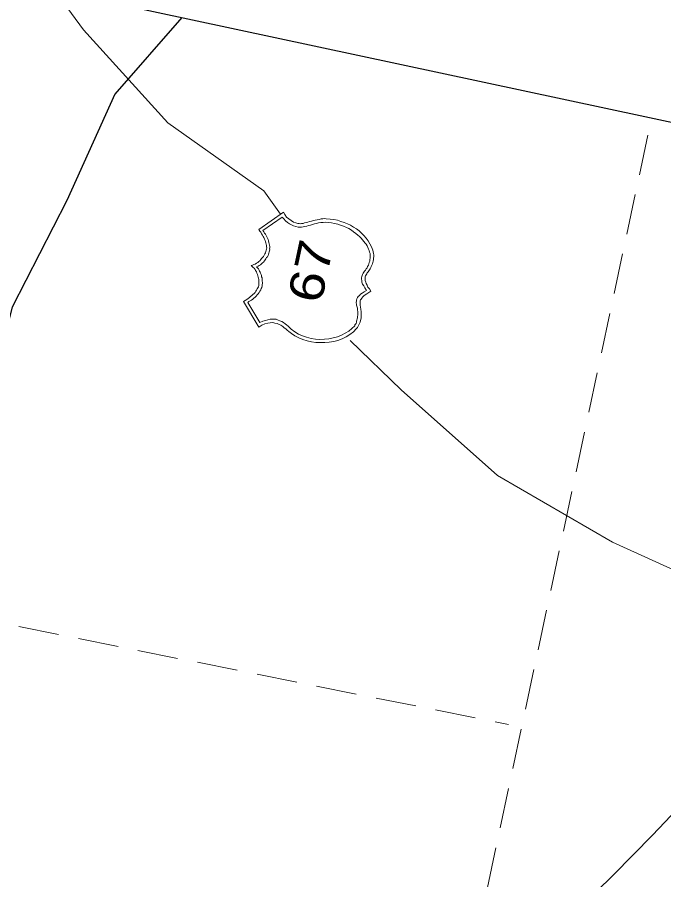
# Model space of a CAD drawing. Extents: x 2363411 to 2369126, y 6976878 to 6988319.
# Drawn here: x 2368374.1 to 2368470, y 6988102.7 to 6988230.5 of the extents above; entities that cross this region are included whole.
import ezdxf

# ---------------------------------------------------------------- set-up
doc = ezdxf.new("R2010")
doc.units = 0
doc.header["$LTSCALE"] = 2
doc.linetypes.add('MEDIUM_DASHED', pattern=[4.5, 3, -1.5])
doc.layers.add('62', color=7, linetype='Continuous', lineweight=13)
doc.layers.add('63', color=7, linetype='Continuous', lineweight=13)

msp = doc.modelspace()

# ---------------------------------------------------------------- linework, layer by layer
at = {"layer": '62', "linetype": 'MEDIUM_DASHED'}
for p, q in [((2368374.263, 6987775.914), (2368468.206, 6988215.584)), ((2368171.397, 6988180.77), (2368446.955, 6988125.71))]:
    msp.add_line(p, q, dxfattribs=at)
at = {"layer": '62'}
msp.add_line((2368410.722, 6988204.783), (2368413.183, 6988201.336), dxfattribs=at)
at = {"layer": '62', "lineweight": 25}
for points in [[(2368004.774, 6987854.862), (2368459.776, 6987757.642), (2368553.719, 6988197.31), (2368098.715, 6988294.53)], [(2368398.516, 6988230.474), (2368388.619, 6988219.148), (2368381.474, 6988203.373), (2368373.402, 6988187.563), (2368367.395, 6988164.505), (2368363.602, 6988150.954), (2368362.368, 6988140.978), (2368360.68, 6988123.828), (2368358.194, 6988112.187), (2368356.9, 6988103.329)]]:
    msp.add_lwpolyline(points, dxfattribs=at)
at = {"layer": '62'}
for points in [[(2368379.725, 6988234.485), (2368383.956, 6988228.661), (2368396.472, 6988214.873), (2368410.722, 6988204.783)], [(2368409.95, 6988184.586), (2368407.685, 6988188.408), (2368407.92, 6988188.542), (2368408.157, 6988188.675), (2368408.352, 6988188.84), (2368408.565, 6988188.976), (2368408.736, 6988189.128), (2368408.909, 6988189.296), (2368409.075, 6988189.422), (2368409.249, 6988189.591), (2368409.396, 6988189.744), (2368409.5, 6988189.908), (2368409.63, 6988190.086), (2368409.711, 6988190.253), (2368409.82, 6988190.436), (2368409.898, 6988190.581), (2368409.94, 6988190.781), (2368409.958, 6988190.982), (2368409.967, 6988191.117), (2368409.934, 6988191.285), (2368409.948, 6988191.466), (2368409.941, 6988191.652), (2368409.892, 6988191.848), (2368409.858, 6988192.015), (2368409.809, 6988192.21), (2368409.759, 6988192.405), (2368409.664, 6988192.609), (2368409.588, 6988192.787), (2368409.464, 6988192.975), (2368409.409, 6988193.146), (2368409.261, 6988193.317), (2368409.131, 6988193.459), (2368408.974, 6988193.585), (2368408.816, 6988193.711), (2368409.016, 6988193.782), (2368409.221, 6988193.88), (2368409.42, 6988193.95), (2368409.606, 6988194.071), (2368409.789, 6988194.169), (2368409.938, 6988194.321), (2368410.103, 6988194.448), (2368410.249, 6988194.601), (2368410.377, 6988194.757), (2368410.524, 6988194.91), (2368410.633, 6988195.093), (2368410.736, 6988195.255), (2368410.825, 6988195.467), (2368410.927, 6988195.607), (2368411.016, 6988195.817), (2368411.059, 6988196.015), (2368411.092, 6988196.169), (2368411.129, 6988196.345), (2368411.096, 6988196.512), (2368411.095, 6988196.721), (2368411.04, 6988196.894), (2368411.01, 6988197.084), (2368410.935, 6988197.262), (2368410.884, 6988197.457), (2368410.785, 6988197.64), (2368410.695, 6988197.865), (2368410.596, 6988198.046), (2368410.502, 6988198.252), (2368410.358, 6988198.443), (2368410.245, 6988198.673), (2368410.098, 6988198.846), (2368409.96, 6988199.057), (2368413.591, 6988201.617), (2368413.813, 6988201.271), (2368414.083, 6988200.915), (2368414.414, 6988200.636), (2368414.756, 6988200.403), (2368415.098, 6988200.17), (2368415.44, 6988200.048), (2368415.721, 6988199.968), (2368415.925, 6988199.945), (2368416.106, 6988199.93), (2368416.299, 6988199.981), (2368416.508, 6988199.982), (2368416.73, 6988200.049), (2368416.971, 6988200.112), (2368417.217, 6988200.178), (2368417.482, 6988200.234), (2368417.773, 6988200.31), (2368418.043, 6988200.392), (2368418.314, 6988200.471), (2368418.623, 6988200.52), (2368418.889, 6988200.577), (2368419.178, 6988200.63), (2368419.434, 6988200.645), (2368419.694, 6988200.683), (2368419.962, 6988200.649), (2368420.532, 6988200.619), (2368421.093, 6988200.546), (2368421.598, 6988200.436), (2368422.116, 6988200.278), (2368422.611, 6988200.126), (2368423.094, 6988199.91), (2368423.555, 6988199.695), (2368424.008, 6988199.439), (2368424.431, 6988199.164), (2368424.825, 6988198.851)], [(2368425.351, 6988197.54), (2368425.145, 6988197.766), (2368424.901, 6988198.027), (2368424.627, 6988198.247), (2368424.334, 6988198.496), (2368424.014, 6988198.721), (2368423.674, 6988198.958), (2368423.309, 6988199.195), (2368422.938, 6988199.391), (2368422.517, 6988199.573), (2368422.091, 6988199.732), (2368421.661, 6988199.87), (2368421.199, 6988199.969), (2368420.709, 6988200.051), (2368420.281, 6988200.096), (2368419.876, 6988200.135), (2368419.506, 6988200.124), (2368419.151, 6988200.084), (2368418.821, 6988200.04), (2368418.484, 6988199.975), (2368418.192, 6988199.9), (2368417.896, 6988199.8), (2368417.598, 6988199.704), (2368417.333, 6988199.644), (2368417.063, 6988199.564), (2368416.798, 6988199.507), (2368416.533, 6988199.449), (2368416.274, 6988199.434), (2368416.041, 6988199.415), (2368415.767, 6988199.426), (2368415.458, 6988199.492), (2368415.117, 6988199.61), (2368414.801, 6988199.749), (2368414.49, 6988199.906), (2368414.189, 6988200.109), (2368413.922, 6988200.373), (2368413.677, 6988200.633), (2368413.438, 6988200.912), (2368410.572, 6988198.904), (2368410.691, 6988198.717), (2368410.819, 6988198.551), (2368410.963, 6988198.361), (2368411.061, 6988198.18), (2368411.156, 6988197.974), (2368411.248, 6988197.77), (2368411.323, 6988197.572), (2368411.393, 6988197.371), (2368411.439, 6988197.154), (2368411.511, 6988196.955), (2368411.556, 6988196.737), (2368411.569, 6988196.574), (2368411.57, 6988196.368), (2368411.56, 6988196.208), (2368411.575, 6988196.066), (2368411.544, 6988195.911), (2368411.511, 6988195.757), (2368411.445, 6988195.564), (2368411.385, 6988195.395), (2368411.325, 6988195.222), (2368411.218, 6988195.036), (2368411.118, 6988194.898), (2368411.01, 6988194.714), (2368410.884, 6988194.557), (2368410.785, 6988194.417), (2368410.628, 6988194.221), (2368410.49, 6988194.111), (2368410.347, 6988193.982), (2368410.18, 6988193.834), (2368410.001, 6988193.756), (2368409.836, 6988193.632), (2368409.609, 6988193.543), (2368409.757, 6988193.372), (2368409.889, 6988193.23), (2368409.987, 6988193.047), (2368410.068, 6988192.891), (2368410.151, 6988192.734), (2368410.211, 6988192.584), (2368410.282, 6988192.387), (2368410.369, 6988192.254), (2368410.374, 6988192.067), (2368410.43, 6988191.895), (2368410.442, 6988191.729), (2368410.474, 6988191.563), (2368410.464, 6988191.403), (2368410.492, 6988191.213), (2368410.482, 6988191.056), (2368410.472, 6988190.894), (2368410.454, 6988190.714), (2368410.407, 6988190.495), (2368410.327, 6988190.33), (2368410.234, 6988190.117), (2368410.126, 6988189.933), (2368409.991, 6988189.731), (2368409.857, 6988189.533), (2368409.713, 6988189.4), (2368409.558, 6988189.204), (2368409.406, 6988189.03), (2368409.236, 6988188.882), (2368409.047, 6988188.761), (2368408.873, 6988188.591), (2368408.664, 6988188.475)], [(2368424.825, 6988198.851), (2368425.189, 6988198.517), (2368425.53, 6988198.168), (2368425.866, 6988197.8), (2368426.164, 6988197.368), (2368426.418, 6988196.944), (2368426.668, 6988196.5), (2368426.776, 6988196.246), (2368426.862, 6988195.998), (2368426.923, 6988195.754), (2368426.941, 6988195.521), (2368426.988, 6988195.305), (2368426.987, 6988195.074), (2368426.979, 6988194.822), (2368426.958, 6988194.622), (2368426.934, 6988194.396), (2368426.863, 6988194.18), (2368426.821, 6988193.984), (2368426.737, 6988193.794), (2368426.621, 6988193.589), (2368426.562, 6988193.416), (2368426.458, 6988193.256), (2368426.356, 6988193.092), (2368426.251, 6988192.93), (2368426.152, 6988192.79), (2368426.029, 6988192.656), (2368425.955, 6988192.509), (2368425.877, 6988192.366), (2368425.796, 6988192.199), (2368425.742, 6988192.049), (2368425.704, 6988191.873), (2368425.711, 6988191.688), (2368425.739, 6988191.498), (2368425.806, 6988191.277), (2368425.878, 6988191.077), (2368426.004, 6988190.797), (2368426.129, 6988190.541), (2368426.35, 6988190.263), (2368426.575, 6988189.916), (2368426.259, 6988189.73), (2368425.986, 6988189.537), (2368425.723, 6988189.386), (2368425.551, 6988189.214), (2368425.381, 6988189.067), (2368425.232, 6988188.914), (2368425.156, 6988188.769), (2368425.057, 6988188.631), (2368425.006, 6988188.5), (2368424.973, 6988188.348), (2368424.971, 6988188.232), (2368424.982, 6988188.07), (2368424.976, 6988187.934), (2368424.992, 6988187.792), (2368425.026, 6988187.625), (2368425.036, 6988187.461), (2368425.081, 6988187.337), (2368425.085, 6988187.152), (2368425.115, 6988186.962), (2368425.142, 6988186.772), (2368425.123, 6988186.567), (2368425.13, 6988186.384), (2368425.125, 6988186.154), (2368425.11, 6988185.973), (2368425.062, 6988185.752), (2368425.025, 6988185.576), (2368424.979, 6988185.357), (2368424.904, 6988185.119), (2368424.796, 6988184.936), (2368424.705, 6988184.724), (2368424.572, 6988184.523), (2368424.411, 6988184.327), (2368423.975, 6988183.892), (2368423.452, 6988183.495), (2368422.898, 6988183.153), (2368422.307, 6988182.866), (2368421.681, 6988182.632), (2368421.071, 6988182.463), (2368420.408, 6988182.374), (2368419.726, 6988182.313), (2368419.081, 6988182.312), (2368418.419, 6988182.337), (2368417.751, 6988182.437), (2368417.113, 6988182.573), (2368416.468, 6988182.778), (2368415.895, 6988183.017), (2368415.319, 6988183.324), (2368414.793, 6988183.666), (2368414.592, 6988183.799), (2368414.395, 6988183.957), (2368414.181, 6988184.142), (2368413.971, 6988184.349), (2368413.733, 6988184.514), (2368413.496, 6988184.702), (2368413.24, 6988184.898), (2368412.962, 6988185), (2368412.666, 6988185.133), (2368412.338, 6988185.203), (2368412.029, 6988185.269), (2368411.653, 6988185.235), (2368411.277, 6988185.198), (2368410.834, 6988185.064)], [(2368408.324, 6988188.273), (2368410.096, 6988185.269), (2368410.531, 6988185.474), (2368410.925, 6988185.597), (2368411.293, 6988185.702), (2368411.629, 6988185.769), (2368411.973, 6988185.765), (2368412.274, 6988185.768), (2368412.547, 6988185.757), (2368412.825, 6988185.653), (2368413.096, 6988185.526), (2368413.352, 6988185.424), (2368413.619, 6988185.275), (2368413.853, 6988185.086), (2368414.072, 6988184.926), (2368414.31, 6988184.736), (2368414.515, 6988184.531), (2368414.749, 6988184.322), (2368415.281, 6988183.907), (2368415.856, 6988183.578), (2368416.415, 6988183.297), (2368417.04, 6988183.094), (2368417.697, 6988182.931), (2368418.36, 6988182.812), (2368419.022, 6988182.785), (2368419.672, 6988182.807), (2368420.353, 6988182.868), (2368421.002, 6988183.006), (2368421.636, 6988183.171), (2368422.238, 6988183.411), (2368422.758, 6988183.692), (2368423.311, 6988184.01), (2368423.76, 6988184.396), (2368424.172, 6988184.815), (2368424.217, 6988184.92), (2368424.307, 6988185.018), (2368424.385, 6988185.161), (2368424.422, 6988185.339), (2368424.45, 6988185.47), (2368424.51, 6988185.643), (2368424.548, 6988185.817), (2368424.564, 6988185.998), (2368424.605, 6988186.195), (2368424.643, 6988186.371), (2368424.615, 6988186.562), (2368424.63, 6988186.742), (2368424.645, 6988186.923), (2368424.612, 6988187.092), (2368424.601, 6988187.256), (2368424.585, 6988187.396), (2368424.531, 6988187.569), (2368424.493, 6988187.714), (2368424.455, 6988187.862), (2368424.44, 6988188.002), (2368424.412, 6988188.192), (2368424.413, 6988188.308), (2368424.422, 6988188.466), (2368424.455, 6988188.62), (2368424.511, 6988188.772), (2368424.602, 6988188.98), (2368424.702, 6988189.12), (2368424.87, 6988189.27), (2368425.027, 6988189.465), (2368425.295, 6988189.639), (2368425.571, 6988189.854), (2368425.909, 6988190.036), (2368425.668, 6988190.408), (2368425.503, 6988190.722), (2368425.353, 6988190.985), (2368425.25, 6988191.258), (2368425.209, 6988191.498), (2368425.18, 6988191.687), (2368425.179, 6988191.893), (2368425.221, 6988192.093), (2368425.281, 6988192.264), (2368425.335, 6988192.414), (2368425.439, 6988192.574), (2368425.543, 6988192.738), (2368425.645, 6988192.898), (2368425.768, 6988193.033), (2368425.875, 6988193.217), (2368426.006, 6988193.398), (2368426.092, 6988193.586), (2368426.222, 6988193.765), (2368426.269, 6988193.986), (2368426.334, 6988194.178), (2368426.404, 6988194.392), (2368426.428, 6988194.618), (2368426.448, 6988194.821), (2368426.474, 6988195.046), (2368426.448, 6988195.256), (2368426.452, 6988195.489), (2368426.364, 6988195.714), (2368426.322, 6988195.952), (2368426.229, 6988196.158), (2368426.143, 6988196.405), (2368426.008, 6988196.641), (2368425.875, 6988196.876), (2368425.731, 6988197.066), (2368425.528, 6988197.296), (2368425.351, 6988197.54)], [(2368408.664, 6988188.475), (2368408.483, 6988188.374), (2368408.324, 6988188.273)], [(2368410.834, 6988185.064), (2368410.405, 6988184.879), (2368409.95, 6988184.586)], [(2368423.495, 6988182.612), (2368431.049, 6988175.317), (2368445.358, 6988162.592), (2368462.419, 6988152.736), (2368475.776, 6988146.66), (2368485.116, 6988127.592), (2368494.927, 6988125.354), (2368500.711, 6988107.416), (2368506.585, 6988092.7), (2368510.293, 6988075.479), (2368509.748, 6988052.675), (2368510.031, 6988033.104), (2368510.965, 6988011.643), (2368511.296, 6987998.756)], [(2368492.126, 6988150.482), (2368487.488, 6988143.215), (2368483.673, 6988134.181), (2368476.579, 6988118.002), (2368468.319, 6988109.277), (2368462.564, 6988103.439), (2368454.914, 6988095.96), (2368443.897, 6988089.32), (2368432.645, 6988085.443), (2368420.226, 6988082.021), (2368405.209, 6988076.579), (2368395.275, 6988071.108), (2368385.769, 6988067.316), (2368374.006, 6988063.41), (2368368.396, 6988060.537), (2368354.465, 6988056.288)]]:
    msp.add_lwpolyline(points, dxfattribs=at)
at = {"layer": '63', "linetype": 'MEDIUM_DASHED'}
for p, q in [((2368374.263, 6987775.914), (2368468.206, 6988215.584)), ((2368171.397, 6988180.77), (2368446.955, 6988125.71))]:
    msp.add_line(p, q, dxfattribs=at)
at = {"layer": '63'}
msp.add_line((2368410.722, 6988204.783), (2368413.183, 6988201.336), dxfattribs=at)
at = {"layer": '63', "lineweight": 25}
for points in [[(2368004.774, 6987854.862), (2368459.776, 6987757.642), (2368553.719, 6988197.31), (2368098.715, 6988294.53)], [(2368398.516, 6988230.474), (2368388.619, 6988219.148), (2368381.474, 6988203.373), (2368373.402, 6988187.563), (2368367.395, 6988164.505), (2368363.602, 6988150.954), (2368362.368, 6988140.978), (2368360.68, 6988123.828), (2368358.194, 6988112.187), (2368356.9, 6988103.329)]]:
    msp.add_lwpolyline(points, dxfattribs=at)
at = {"layer": '63'}
for points in [[(2368379.725, 6988234.485), (2368383.956, 6988228.661), (2368396.472, 6988214.873), (2368410.722, 6988204.783)], [(2368409.95, 6988184.586), (2368407.685, 6988188.408), (2368407.92, 6988188.542), (2368408.157, 6988188.675), (2368408.352, 6988188.84), (2368408.565, 6988188.976), (2368408.736, 6988189.128), (2368408.909, 6988189.296), (2368409.075, 6988189.422), (2368409.249, 6988189.591), (2368409.396, 6988189.744), (2368409.5, 6988189.908), (2368409.63, 6988190.086), (2368409.711, 6988190.253), (2368409.82, 6988190.436), (2368409.898, 6988190.581), (2368409.94, 6988190.781), (2368409.958, 6988190.982), (2368409.967, 6988191.117), (2368409.934, 6988191.285), (2368409.948, 6988191.466), (2368409.941, 6988191.652), (2368409.892, 6988191.848), (2368409.858, 6988192.015), (2368409.809, 6988192.21), (2368409.759, 6988192.405), (2368409.664, 6988192.609), (2368409.588, 6988192.787), (2368409.464, 6988192.975), (2368409.409, 6988193.146), (2368409.261, 6988193.317), (2368409.131, 6988193.459), (2368408.974, 6988193.585), (2368408.816, 6988193.711), (2368409.016, 6988193.782), (2368409.221, 6988193.88), (2368409.42, 6988193.95), (2368409.606, 6988194.071), (2368409.789, 6988194.169), (2368409.938, 6988194.321), (2368410.103, 6988194.448), (2368410.249, 6988194.601), (2368410.377, 6988194.757), (2368410.524, 6988194.91), (2368410.633, 6988195.093), (2368410.736, 6988195.255), (2368410.825, 6988195.467), (2368410.927, 6988195.607), (2368411.016, 6988195.817), (2368411.059, 6988196.015), (2368411.092, 6988196.169), (2368411.129, 6988196.345), (2368411.096, 6988196.512), (2368411.095, 6988196.721), (2368411.04, 6988196.894), (2368411.01, 6988197.084), (2368410.935, 6988197.262), (2368410.884, 6988197.457), (2368410.785, 6988197.64), (2368410.695, 6988197.865), (2368410.596, 6988198.046), (2368410.502, 6988198.252), (2368410.358, 6988198.443), (2368410.245, 6988198.673), (2368410.098, 6988198.846), (2368409.96, 6988199.057), (2368413.591, 6988201.617), (2368413.813, 6988201.271), (2368414.083, 6988200.915), (2368414.414, 6988200.636), (2368414.756, 6988200.403), (2368415.098, 6988200.17), (2368415.44, 6988200.048), (2368415.721, 6988199.968), (2368415.925, 6988199.945), (2368416.106, 6988199.93), (2368416.299, 6988199.981), (2368416.508, 6988199.982), (2368416.73, 6988200.049), (2368416.971, 6988200.112), (2368417.217, 6988200.178), (2368417.482, 6988200.234), (2368417.773, 6988200.31), (2368418.043, 6988200.392), (2368418.314, 6988200.471), (2368418.623, 6988200.52), (2368418.889, 6988200.577), (2368419.178, 6988200.63), (2368419.434, 6988200.645), (2368419.694, 6988200.683), (2368419.962, 6988200.649), (2368420.532, 6988200.619), (2368421.093, 6988200.546), (2368421.598, 6988200.436), (2368422.116, 6988200.278), (2368422.611, 6988200.126), (2368423.094, 6988199.91), (2368423.555, 6988199.695), (2368424.008, 6988199.439), (2368424.431, 6988199.164), (2368424.825, 6988198.851)], [(2368425.351, 6988197.54), (2368425.145, 6988197.766), (2368424.901, 6988198.027), (2368424.627, 6988198.247), (2368424.334, 6988198.496), (2368424.014, 6988198.721), (2368423.674, 6988198.958), (2368423.309, 6988199.195), (2368422.938, 6988199.391), (2368422.517, 6988199.573), (2368422.091, 6988199.732), (2368421.661, 6988199.87), (2368421.199, 6988199.969), (2368420.709, 6988200.051), (2368420.281, 6988200.096), (2368419.876, 6988200.135), (2368419.506, 6988200.124), (2368419.151, 6988200.084), (2368418.821, 6988200.04), (2368418.484, 6988199.975), (2368418.192, 6988199.9), (2368417.896, 6988199.8), (2368417.598, 6988199.704), (2368417.333, 6988199.644), (2368417.063, 6988199.564), (2368416.798, 6988199.507), (2368416.533, 6988199.449), (2368416.274, 6988199.434), (2368416.041, 6988199.415), (2368415.767, 6988199.426), (2368415.458, 6988199.492), (2368415.117, 6988199.61), (2368414.801, 6988199.749), (2368414.49, 6988199.906), (2368414.189, 6988200.109), (2368413.922, 6988200.373), (2368413.677, 6988200.633), (2368413.438, 6988200.912), (2368410.572, 6988198.904), (2368410.691, 6988198.717), (2368410.819, 6988198.551), (2368410.963, 6988198.361), (2368411.061, 6988198.18), (2368411.156, 6988197.974), (2368411.248, 6988197.77), (2368411.323, 6988197.572), (2368411.393, 6988197.371), (2368411.439, 6988197.154), (2368411.511, 6988196.955), (2368411.556, 6988196.737), (2368411.569, 6988196.574), (2368411.57, 6988196.368), (2368411.56, 6988196.208), (2368411.575, 6988196.066), (2368411.544, 6988195.911), (2368411.511, 6988195.757), (2368411.445, 6988195.564), (2368411.385, 6988195.395), (2368411.325, 6988195.222), (2368411.218, 6988195.036), (2368411.118, 6988194.898), (2368411.01, 6988194.714), (2368410.884, 6988194.557), (2368410.785, 6988194.417), (2368410.628, 6988194.221), (2368410.49, 6988194.111), (2368410.347, 6988193.982), (2368410.18, 6988193.834), (2368410.001, 6988193.756), (2368409.836, 6988193.632), (2368409.609, 6988193.543), (2368409.757, 6988193.372), (2368409.889, 6988193.23), (2368409.987, 6988193.047), (2368410.068, 6988192.891), (2368410.151, 6988192.734), (2368410.211, 6988192.584), (2368410.282, 6988192.387), (2368410.369, 6988192.254), (2368410.374, 6988192.067), (2368410.43, 6988191.895), (2368410.442, 6988191.729), (2368410.474, 6988191.563), (2368410.464, 6988191.403), (2368410.492, 6988191.213), (2368410.482, 6988191.056), (2368410.472, 6988190.894), (2368410.454, 6988190.714), (2368410.407, 6988190.495), (2368410.327, 6988190.33), (2368410.234, 6988190.117), (2368410.126, 6988189.933), (2368409.991, 6988189.731), (2368409.857, 6988189.533), (2368409.713, 6988189.4), (2368409.558, 6988189.204), (2368409.406, 6988189.03), (2368409.236, 6988188.882), (2368409.047, 6988188.761), (2368408.873, 6988188.591), (2368408.664, 6988188.475)], [(2368424.825, 6988198.851), (2368425.189, 6988198.517), (2368425.53, 6988198.168), (2368425.866, 6988197.8), (2368426.164, 6988197.368), (2368426.418, 6988196.944), (2368426.668, 6988196.5), (2368426.776, 6988196.246), (2368426.862, 6988195.998), (2368426.923, 6988195.754), (2368426.941, 6988195.521), (2368426.988, 6988195.305), (2368426.987, 6988195.074), (2368426.979, 6988194.822), (2368426.958, 6988194.622), (2368426.934, 6988194.396), (2368426.863, 6988194.18), (2368426.821, 6988193.984), (2368426.737, 6988193.794), (2368426.621, 6988193.589), (2368426.562, 6988193.416), (2368426.458, 6988193.256), (2368426.356, 6988193.092), (2368426.251, 6988192.93), (2368426.152, 6988192.79), (2368426.029, 6988192.656), (2368425.955, 6988192.509), (2368425.877, 6988192.366), (2368425.796, 6988192.199), (2368425.742, 6988192.049), (2368425.704, 6988191.873), (2368425.711, 6988191.688), (2368425.739, 6988191.498), (2368425.806, 6988191.277), (2368425.878, 6988191.077), (2368426.004, 6988190.797), (2368426.129, 6988190.541), (2368426.35, 6988190.263), (2368426.575, 6988189.916), (2368426.259, 6988189.73), (2368425.986, 6988189.537), (2368425.723, 6988189.386), (2368425.551, 6988189.214), (2368425.381, 6988189.067), (2368425.232, 6988188.914), (2368425.156, 6988188.769), (2368425.057, 6988188.631), (2368425.006, 6988188.5), (2368424.973, 6988188.348), (2368424.971, 6988188.232), (2368424.982, 6988188.07), (2368424.976, 6988187.934), (2368424.992, 6988187.792), (2368425.026, 6988187.625), (2368425.036, 6988187.461), (2368425.081, 6988187.337), (2368425.085, 6988187.152), (2368425.115, 6988186.962), (2368425.142, 6988186.772), (2368425.123, 6988186.567), (2368425.13, 6988186.384), (2368425.125, 6988186.154), (2368425.11, 6988185.973), (2368425.062, 6988185.752), (2368425.025, 6988185.576), (2368424.979, 6988185.357), (2368424.904, 6988185.119), (2368424.796, 6988184.936), (2368424.705, 6988184.724), (2368424.572, 6988184.523), (2368424.411, 6988184.327), (2368423.975, 6988183.892), (2368423.452, 6988183.495), (2368422.898, 6988183.153), (2368422.307, 6988182.866), (2368421.681, 6988182.632), (2368421.071, 6988182.463), (2368420.408, 6988182.374), (2368419.726, 6988182.313), (2368419.081, 6988182.312), (2368418.419, 6988182.337), (2368417.751, 6988182.437), (2368417.113, 6988182.573), (2368416.468, 6988182.778), (2368415.895, 6988183.017), (2368415.319, 6988183.324), (2368414.793, 6988183.666), (2368414.592, 6988183.799), (2368414.395, 6988183.957), (2368414.181, 6988184.142), (2368413.971, 6988184.349), (2368413.733, 6988184.514), (2368413.496, 6988184.702), (2368413.24, 6988184.898), (2368412.962, 6988185), (2368412.666, 6988185.133), (2368412.338, 6988185.203), (2368412.029, 6988185.269), (2368411.653, 6988185.235), (2368411.277, 6988185.198), (2368410.834, 6988185.064)], [(2368408.324, 6988188.273), (2368410.096, 6988185.269), (2368410.531, 6988185.474), (2368410.925, 6988185.597), (2368411.293, 6988185.702), (2368411.629, 6988185.769), (2368411.973, 6988185.765), (2368412.274, 6988185.768), (2368412.547, 6988185.757), (2368412.825, 6988185.653), (2368413.096, 6988185.526), (2368413.352, 6988185.424), (2368413.619, 6988185.275), (2368413.853, 6988185.086), (2368414.072, 6988184.926), (2368414.31, 6988184.736), (2368414.515, 6988184.531), (2368414.749, 6988184.322), (2368415.281, 6988183.907), (2368415.856, 6988183.578), (2368416.415, 6988183.297), (2368417.04, 6988183.094), (2368417.697, 6988182.931), (2368418.36, 6988182.812), (2368419.022, 6988182.785), (2368419.672, 6988182.807), (2368420.353, 6988182.868), (2368421.002, 6988183.006), (2368421.636, 6988183.171), (2368422.238, 6988183.411), (2368422.758, 6988183.692), (2368423.311, 6988184.01), (2368423.76, 6988184.396), (2368424.172, 6988184.815), (2368424.217, 6988184.92), (2368424.307, 6988185.018), (2368424.385, 6988185.161), (2368424.422, 6988185.339), (2368424.45, 6988185.47), (2368424.51, 6988185.643), (2368424.548, 6988185.817), (2368424.564, 6988185.998), (2368424.605, 6988186.195), (2368424.643, 6988186.371), (2368424.615, 6988186.562), (2368424.63, 6988186.742), (2368424.645, 6988186.923), (2368424.612, 6988187.092), (2368424.601, 6988187.256), (2368424.585, 6988187.396), (2368424.531, 6988187.569), (2368424.493, 6988187.714), (2368424.455, 6988187.862), (2368424.44, 6988188.002), (2368424.412, 6988188.192), (2368424.413, 6988188.308), (2368424.422, 6988188.466), (2368424.455, 6988188.62), (2368424.511, 6988188.772), (2368424.602, 6988188.98), (2368424.702, 6988189.12), (2368424.87, 6988189.27), (2368425.027, 6988189.465), (2368425.295, 6988189.639), (2368425.571, 6988189.854), (2368425.909, 6988190.036), (2368425.668, 6988190.408), (2368425.503, 6988190.722), (2368425.353, 6988190.985), (2368425.25, 6988191.258), (2368425.209, 6988191.498), (2368425.18, 6988191.687), (2368425.179, 6988191.893), (2368425.221, 6988192.093), (2368425.281, 6988192.264), (2368425.335, 6988192.414), (2368425.439, 6988192.574), (2368425.543, 6988192.738), (2368425.645, 6988192.898), (2368425.768, 6988193.033), (2368425.875, 6988193.217), (2368426.006, 6988193.398), (2368426.092, 6988193.586), (2368426.222, 6988193.765), (2368426.269, 6988193.986), (2368426.334, 6988194.178), (2368426.404, 6988194.392), (2368426.428, 6988194.618), (2368426.448, 6988194.821), (2368426.474, 6988195.046), (2368426.448, 6988195.256), (2368426.452, 6988195.489), (2368426.364, 6988195.714), (2368426.322, 6988195.952), (2368426.229, 6988196.158), (2368426.143, 6988196.405), (2368426.008, 6988196.641), (2368425.875, 6988196.876), (2368425.731, 6988197.066), (2368425.528, 6988197.296), (2368425.351, 6988197.54)], [(2368408.664, 6988188.475), (2368408.483, 6988188.374), (2368408.324, 6988188.273)], [(2368410.834, 6988185.064), (2368410.405, 6988184.879), (2368409.95, 6988184.586)], [(2368423.495, 6988182.612), (2368431.049, 6988175.317), (2368445.358, 6988162.592), (2368462.419, 6988152.736), (2368475.776, 6988146.66), (2368485.116, 6988127.592), (2368494.927, 6988125.354), (2368500.711, 6988107.416), (2368506.585, 6988092.7), (2368510.293, 6988075.479), (2368509.748, 6988052.675), (2368510.031, 6988033.104), (2368510.965, 6988011.643), (2368511.296, 6987998.756)], [(2368492.126, 6988150.482), (2368487.488, 6988143.215), (2368483.673, 6988134.181), (2368476.579, 6988118.002), (2368468.319, 6988109.277), (2368462.564, 6988103.439), (2368454.914, 6988095.96), (2368443.897, 6988089.32), (2368432.645, 6988085.443), (2368420.226, 6988082.021), (2368405.209, 6988076.579), (2368395.275, 6988071.108), (2368385.769, 6988067.316), (2368374.006, 6988063.41), (2368368.396, 6988060.537), (2368354.465, 6988056.288)]]:
    msp.add_lwpolyline(points, dxfattribs=at)

# ---------------------------------------------------------------- texts
at = {"layer": '62', "width": 1.2}
msp.add_text('67', height=5.099, rotation=77.939, dxfattribs=at).set_placement((2368419.173, 6988187.909))
at = {"layer": '63', "width": 1.2}
msp.add_text('67', height=5.099, rotation=77.939, dxfattribs=at).set_placement((2368419.173, 6988187.909))

doc.saveas('drawing.dxf')
